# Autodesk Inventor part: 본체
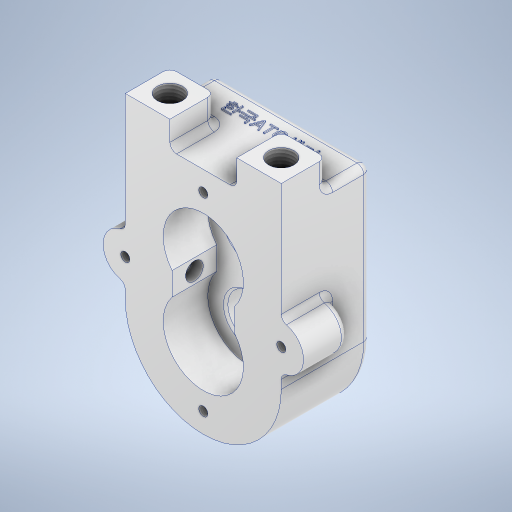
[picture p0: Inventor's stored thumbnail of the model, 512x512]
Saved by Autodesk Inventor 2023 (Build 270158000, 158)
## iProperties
Created: 2024-03
Part Number: 본체
Material: 알루미늄 6061
Document SubType Name: Modeling
Designer: asung
Density: 2.7 g/cm^3
Appearance: 알루미늄 - 평지
Author: asung
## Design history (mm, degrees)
sketch "스케치1"
  geometry: L1 (0, 0)-(0, 33); L2 (0, 33)-(0, 68); L3 (-35, 68)-(35, 68); L4 (35, 68)-(35, 0); L5 (35, 0)-(-35, 0); L6 (-35, 0)-(-35, 68); L7 (0, 0)-(0, -26); C1 r 35 at (0, 0); 3 further points
  constraints: 14 end point, 2 coincident, 2 parallel, 2 vertical, 1 centre point, 1 horizontal, 1 midpoint, 1 perpendicular, 1 point on line
  dimensions: "d1" = 33 distance of L1.start L1.end; "d2" = 35 distance of L1.end L2.end; "d5" = 70 diameter of C1; "d6" = 70 distance of L4.end L5.end; "d7" = 68 distance of L3.end L4.end; "d8" = 26 distance of L7.start L7.end
extrude "돌출1" new body sketch "스케치1" stored distance "d9" = 40; taper "d10" = 0 deg
sketch "스케치3"
  geometry: L1 (0, 0)-(0, 33); L2 (14, 0)-(14, 33); L3 (-14, 0)-(-14, 33); C1 r 18 at (0, 0); C2 r 18 at (0, 33); 5 further points
  constraints: 6 end point, 2 centre point, 2 coincident, 2 parallel, 1 vertical
  dimensions: "d12" = 36 diameter of C1; "d13" = 33 distance of L1.start L1.end; "d14" = 36 diameter of C2; "d15" = 28 distance of L2.start L3.start; "d16" = 28 distance between parallel lines of L2 L3; "d17" = 33 distance of L2.start L2.end; "d18" = 28 distance of L2.end L3.end; "d19" = 14 distance between parallel lines of L1 L2; "d20" = 35.8469 distance of point (0, 0) L2.end
extrude "돌출2" cut sketch "스케치3" distance "d21" = 20; taper "d22" = 0 deg
node "작업 평면1"
sketch "스케치6"
  geometry: C1 r 7.5 at (0, 33) reference; 2 further points
  constraints: 1 coincident
hole "구멍2" sketch "스케치6" at (0, 33) diameter "d35" = 20; stored, may be unused: countersink angle "d39" = 90 deg, drill point angle "d41" = 0 deg; dims "d36" = 6, "d37" = 25, "d38" = 7.3, "d40" = 10
sketch "스케치7"
  geometry: A1 r 18 centre (0, 0) between (-14, 11.314) and (14, 11.314) reference; 2 further points
  constraints: 1 coincident
hole "구멍3" sketch "스케치7" at (0, 0) diameter "d42" = 20; stored, may be unused: countersink angle "d46" = 90 deg, drill point angle "d48" = 0 deg; dims "d43" = 6, "d44" = 4, "d45" = 2, "d47" = 10
sketch "스케치8"
  geometry: L1 (0, 0)-(0, -26); L2 (35, 68)-(-35, 68) reference; L3 (-35, 68)-(-35, 0) reference; L4 (35, 0)-(35, 68) reference; L5 (-14, 11.314)-(-14, 21.686) reference; L6 (14, 21.686)-(14, 11.314) reference; L7 (0, 33)-(0, 59); A1 r 35 centre (0, 0) between (-35, 0) and (35, 0) reference; A2 r 18 centre (0, 0) between (-14, 11.314) and (14, 11.314) reference; A3 r 18 centre (0, 33) between (14, 21.686) and (-14, 21.686) reference; 2 further points
  constraints: 4 end point, 2 coincident, 2 vertical
  dimensions: "d49" = 26 distance of L1.start L1.end; "d50" = 26 distance of L7.start L7.end
  node "투영된 루프3"
chamfer "모따기2" distance "d54" = 1; stored, may be unused: second distance "d55" = 2, angle "d56" = 30 deg
hole "구멍4" sketch "스케치8" diameter "d57" = 4.134; stored, may be unused: countersink angle "d61" = 90 deg, drill point angle "d63" = 118 deg; dims "d58" = 10, "d59" = 4, "d60" = 2, "d62" = 12
sketch "스케치9"
  geometry: L1 (35, 68)-(-35, 68) reference; L2 (-35, 68)-(-35, 0) reference; L3 (35, 0)-(35, 68) reference; L4 (0, 0)-(0, 33); C1 r 26 at (0, 33); A1 r 35 centre (0, 0) between (-35, 0) and (35, 0) reference; 1 further point
  constraints: 2 end point, 1 centre point, 1 coincident, 1 vertical
  dimensions: "d65" = 33 distance of L4.start L4.end; "d66" = 52 diameter of C1
extrude "돌출4" join sketch "스케치9" distance "d67" = 3.3; taper "d68" = 0 deg
sketch "스케치10"
  geometry: C1 r 26 at (0, 0) reference; C2 r 16 at (0, 0); 1 further point
  constraints: 1 centre point, 1 coincident
  dimensions: "d69" = 32 diameter of C2
extrude "돌출5" join sketch "스케치10" distance "d70" = 4; taper "d71" = 0 deg
sketch "스케치11"
  geometry: C1 r 16 at (0, 0) reference; 2 further points
  constraints: 1 coincident
hole "구멍5" sketch "스케치11" at (0, 0) diameter "d72" = 15; stored, may be unused: countersink angle "d76" = 90 deg, drill point angle "d78" = 0 deg; dims "d73" = 10, "d74" = 25, "d75" = 7.3, "d77" = 80
fillet "모깎기2" dims "d79" = 3
chamfer "모따기3" distance "d80" = 1; stored, may be unused: second distance "d81" = 2, angle "d82" = 30 deg
chamfer "모따기4" distance "d83" = 0.7; stored, may be unused: second distance "d84" = 2, angle "d85" = 30 deg
sketch "스케치13" dims "d86" = 42
  geometry: C1 r 12.5 at (0, 0) reference; C2 r 16 at (0, 0) reference; C3 r 26 at (0, 0) reference; 3 further points
  constraints: 1 coincident, 1 vertical alignment, 2 other
hole "구멍6" sketch "스케치13" at (0, 21) diameter "d87" = 3.242; stored, may be unused: countersink angle "d91" = 90 deg, drill point angle "d93" = 118 deg; dims "d88" = 8, "d89" = 25, "d90" = 7.3, "d92" = 10
sketch "스케치14"
  geometry: L1 (-14, 11.314)-(-14, 21.686) reference; L2 (14, 21.686)-(14, 11.314) reference; L3 (35, 68)-(-35, 68) reference; L4 (-35, 68)-(-35, 0) reference; L5 (35, 0)-(35, 68) reference; L6 (35, 68)-(15, 68); L7 (15, 68)-(15, 80); L8 (15, 80)-(35, 80); L9 (35, 80)-(35, 68); L10 (-35, 68)-(-15, 68); L11 (-15, 68)-(-15, 80); L12 (-15, 80)-(-35, 80); L13 (-35, 80)-(-35, 68); L14 (-35, 80)-(-35, 16.5); C1 r 2.067 at (0, -26) reference; C2 r 2.067 at (0, 59) reference; C3 r 10 at (-35, 16.5); A1 r 18 centre (0, 33) between (14, 21.686) and (-14, 21.686) reference; A2 r 18 centre (0, 0) between (-14, 11.314) and (14, 11.314) reference; A3 r 35 centre (0, 0) between (-35, 0) and (35, 0) reference; 5 further points
  constraints: 18 end point, 4 parallel, 2 horizontal, 2 perpendicular, 1 centre point, 1 coincident, 1 point on line
  dimensions: "d97" = 20 distance of L7.end L8.end; "d98" = 12 distance of L6.end L7.end; "d99" = 20 distance of L12.end L11.end; "d100" = 12 distance of L11.end L10.end; "d104" = 10 radius of C3; "d105" = 63.5 distance of L14.end L12.end
  node "투영된 루프7"
extrude "돌출6" join sketch "스케치14" distance "d106" = 20; taper "d107" = 0 deg
extrude "돌출7" join sketch "스케치14" distance "d108" = 20; taper "d109" = 0 deg
sketch "스케치15"
  geometry: C1 r 11 at (0, 0) reference; 2 further points
  constraints: 1 coincident
hole "구멍7" sketch "스케치15" at (0, 0) diameter "d110" = 14; stored, may be unused: countersink angle "d114" = 90 deg, drill point angle "d116" = 120 deg; dims "d111" = 8, "d112" = 4, "d113" = 2, "d115" = 10
fillet "모깎기3" dims "d117" = 3
fillet "모깎기4" dims "d118" = 3
fillet "모깎기5" dims "d119" = 3
fillet "모깎기6" dims "d120" = 3
fillet "모깎기7" dims "d121" = 3
sketch "스케치16"
  geometry: A1 r 10 centre (-35, 16.5) between (-37.308, 26.23) and (-37.308, 6.77) reference; A2 r 10 centre (35, 16.5) between (37.308, 6.77) and (37.308, 26.23) reference; 3 further points
  constraints: 2 coincident
hole "구멍8" sketch "스케치16" at (-35, 16.5), (35, 16.5) diameter "d122" = 4.134; stored, may be unused: countersink angle "d126" = 90 deg, drill point angle "d128" = 118 deg; dims "d123" = 10, "d124" = 4, "d125" = 2, "d127" = 12
sketch "스케치17"
  geometry: L1 (57, 0)-(49.308, 0) reference; 2 further points
  constraints: 1 vertical alignment, 1 other
  dimensions: "d129" = 30 distance from line of point (12, 30) L1
feature "엠보싱1" sketch "스케치17" dims "d1" = 33, "d12" = 36, "d13" = 33, "d14" = 36, "d15" = 28, "d16" = 28, "d17" = 33, "d18" = 28, "d19" = 14, "d20" = 35.8469, "d130" = 0.5, "d131" = 0
sketch "스케치19"
  geometry: L1 (3, 20)-(17, 20) reference; L2 (0, 0)-(0, 17) reference; L3 (20, 0)-(0, 0) reference; L4 (20, 0)-(20, 17) reference; L5 (53, 20)-(67, 20) reference; L6 (50, 0)-(50, 17) reference; L7 (70, 0)-(50, 0) reference; L8 (70, 0)-(70, 17) reference; L9 (10, 0)-(10, 10); L10 (60, 0)-(60, 10); A1 r 3 centre (17, 17) between (20, 17) and (17, 20) reference; A2 r 3 centre (3, 17) between (3, 20) and (0, 17) reference; A3 r 3 centre (67, 17) between (70, 17) and (67, 20) reference; A4 r 3 centre (53, 17) between (53, 20) and (50, 17) reference; 3 further points
  constraints: 4 end point, 2 coincident, 2 midpoint, 2 vertical
  dimensions: "d132" = 10 distance of L9.start L9.end; "d133" = 10 distance of L10.start L10.end
hole "구멍9" sketch "스케치19" at (10, 10), (60, 10) diameter "d134" = 10.7188; stored, may be unused: countersink angle "d140" = 82 deg, drill point angle "d142" = 0 deg; dims "d135" = 8.60806, "d136" = 0.62479, "d137" = 10.82065, "d138" = 4, "d139" = 2, "d141" = 16
sketch "스케치20"
  geometry: L1 (20, -22.627)-(20, 0) reference; L2 (20, 0)-(20, 10.373) reference; L3 (20, 10.373)-(20, 33) reference; L4 (20, 33)-(0, 33) reference; L5 (0, 33)-(0, 57.45) reference; L6 (0, 57.45)-(17, 57.45) reference; L7 (21.472, 56.686)-(30.254, 56.686) reference; L8 (30.254, 56.686)-(30.254, 57.186) reference; L9 (30.254, 57.186)-(30.648, 57.186) reference; L10 (30.648, 57.186)-(30.648, 56.686) reference; L11 (30.648, 56.686)-(37, 56.686) reference; L12 (40, 53.686)-(40, 47.083) reference; L13 (43, 43.595)-(43.3, 43.595) reference; L14 (43.3, 43.595)-(43.3, 29.432) reference; L15 (43.3, 29.432)-(46.3, 29.432) reference; L16 (47.3, 27.071)-(47.3, 16.301) reference; L17 (46.3, 13.94)-(43.3, 13.94) reference; L18 (43.3, 13.94)-(43.3, -0.223) reference; L19 (43.3, -0.223)-(43, -0.223) reference; L20 (40, -3.711)-(40, -40.089) reference; L21 (37, -43.392)-(0, -43.392) reference; L22 (0, -43.392)-(0, -22.627) reference; L23 (0, -22.627)-(20, -22.627) reference; L24 (20, 0)-(0, 0) reference; L25 (0, 0)-(0, 10.373) reference; L26 (0, 10.373)-(20, 10.373) reference; L27 (0, 5.186)-(10, 5.186); A1 r 3 centre (37, 53.686) between (40, 53.686) and (37, 56.686) reference; 2 further points
  constraints: 2 end point, 1 coincident, 1 horizontal, 1 midpoint, 6 other
  dimensions: "d143" = 10 distance of L27.start L27.end
hole "구멍10" sketch "스케치20" at (10, 5.186) diameter "d144" = 8; stored, may be unused: countersink angle "d148" = 90 deg, drill point angle "d150" = 0 deg; dims "d145" = 8.608, "d146" = 4, "d147" = 2, "d149" = 5
node "솔리드1"
pattern_circular "원형 패턴1" dims angle "d95" = 360 deg
mirror "미러1"
mirror "미러2"
node "투영된 루프4"
node "투영된 루프5"
node "투영된 루프8"
node "투영된 루프9"
node "절단 모서리 투영2"
node "절단 모서리 투영3"
feature "A9D066F2-1C7D-4E18-AEED-F7BC21143FA4" dims "d35" = 20, "d36" = 6, "d37" = 25, "d38" = 7.3, "d39" = 90 deg, "d40" = 10, "d41" = 0
